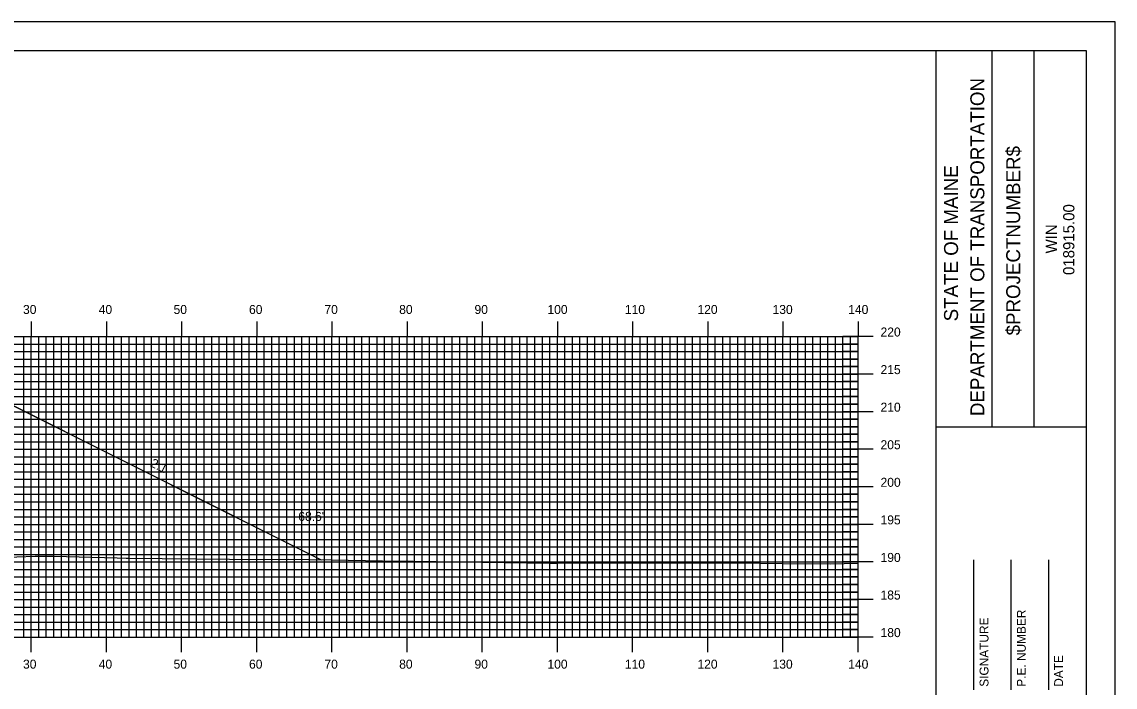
# Model space of a CAD drawing. Extents: x 1810980 to 1811323, y 442591 to 442811.
# Drawn here: x 1811174.6 to 1811320.1, y 442722 to 442810.5 of the extents above; entities that cross this region are included whole.
import ezdxf

# ---------------------------------------------------------------- set-up
doc = ezdxf.new("R2010")
doc.units = 0
for name, color, linetype in [('ANNOTATION', 7, 'Continuous'), ('BORDER', 7, 'Continuous'), ('D_Roadway_Centerline', 7, 'Continuous'), ('D_Roadway_SlopeLines', 7, 'Continuous'), ('D_Text_Standard', 7, 'Continuous'), ('H_V ANNOTATION', 7, 'Continuous'), ('MAJOR', 7, 'Continuous'), ('MINOR', 7, 'Continuous'), ('PLOT BOUNDARY', 7, 'Continuous'), ('S_Roadway_Centerline', 7, 'Continuous')]:
    doc.layers.add(name, color=color, linetype=linetype)

msp = doc.modelspace()

# ---------------------------------------------------------------- linework, layer by layer
at = {"layer": 'BORDER'}
for p, q in [((1811296.29, 442596.67), (1811296.29, 442806.67)), ((1811303.75, 442756.66), (1811303.75, 442806.66)), ((1811309.34, 442756.66), (1811309.34, 442806.66)), ((1811296.29, 442756.65), (1811316.29, 442756.65)), ((1811301.29, 442721.67), (1811301.29, 442738.97)), ((1811306.29, 442721.67), (1811306.29, 442738.97)), ((1811311.29, 442721.67), (1811311.29, 442738.97))]:
    msp.add_line(p, q, dxfattribs=at)
msp.add_lwpolyline([(1810996.29, 442596.67), (1811316.29, 442596.67), (1811316.29, 442806.67), (1810996.29, 442806.67)], close=True, dxfattribs=at)
at = {"layer": 'D_Roadway_Centerline'}
msp.add_lwpolyline([(1811076.55, 442740.06), (1811117.68, 442760.62), (1811122.89, 442763.23), (1811125.89, 442763.29), (1811133.89, 442763.45), (1811145.89, 442762.87), (1811157.89, 442762.29), (1811165.89, 442761.91), (1811168.89, 442761.77), (1811174.42, 442759), (1811214.48, 442738.97)], dxfattribs=at)
at = {"layer": 'D_Roadway_SlopeLines'}
msp.add_lwpolyline([(1811168.89, 442761.77), (1811214.48, 442738.97)], dxfattribs=at)
at = {"layer": 'MAJOR'}
for p, q in [((1811175.89, 442770.67), (1811175.89, 442768.67)), ((1811185.89, 442770.67), (1811185.89, 442768.67)), ((1811195.89, 442770.67), (1811195.89, 442768.67)), ((1811205.89, 442770.67), (1811205.89, 442768.67)), ((1811215.89, 442770.67), (1811215.89, 442768.67)), ((1811225.89, 442770.67), (1811225.89, 442768.67)), ((1811235.89, 442770.67), (1811235.89, 442768.67)), ((1811245.89, 442770.67), (1811245.89, 442768.67)), ((1811255.89, 442770.67), (1811255.89, 442768.67)), ((1811265.89, 442770.67), (1811265.89, 442768.67)), ((1811275.89, 442770.67), (1811275.89, 442768.67)), ((1811285.89, 442770.67), (1811285.89, 442768.67)), ((1811005.89, 442768.67), (1811285.89, 442768.67)), ((1811005.89, 442768.67), (1811285.89, 442768.67)), ((1811175.89, 442728.67), (1811175.89, 442768.67)), ((1811185.89, 442728.67), (1811185.89, 442768.67)), ((1811195.89, 442728.67), (1811195.89, 442768.67)), ((1811205.89, 442728.67), (1811205.89, 442768.67)), ((1811215.89, 442728.67), (1811215.89, 442768.67)), ((1811225.89, 442728.67), (1811225.89, 442768.67)), ((1811235.89, 442728.67), (1811235.89, 442768.67)), ((1811245.89, 442728.67), (1811245.89, 442768.67)), ((1811255.89, 442728.67), (1811255.89, 442768.67)), ((1811265.89, 442728.67), (1811265.89, 442768.67)), ((1811275.89, 442728.67), (1811275.89, 442768.67)), ((1811287.89, 442768.67), (1811283.89, 442768.67)), ((1811285.89, 442728.67), (1811285.89, 442768.67)), ((1811285.89, 442728.67), (1811285.89, 442768.67)), ((1811005.89, 442763.67), (1811285.89, 442763.67)), ((1811287.89, 442763.67), (1811283.89, 442763.67)), ((1811005.89, 442758.67), (1811285.89, 442758.67)), ((1811287.89, 442758.67), (1811283.89, 442758.67)), ((1811005.89, 442753.67), (1811285.89, 442753.67)), ((1811287.89, 442753.67), (1811283.89, 442753.67)), ((1811005.89, 442748.67), (1811285.89, 442748.67)), ((1811287.89, 442748.67), (1811283.89, 442748.67)), ((1811005.89, 442743.67), (1811285.89, 442743.67)), ((1811287.89, 442743.67), (1811283.89, 442743.67)), ((1811005.89, 442738.67), (1811285.89, 442738.67)), ((1811287.89, 442738.67), (1811283.89, 442738.67)), ((1811005.89, 442733.67), (1811285.89, 442733.67)), ((1811287.89, 442733.67), (1811283.89, 442733.67)), ((1811005.89, 442728.67), (1811285.89, 442728.67)), ((1811005.89, 442728.67), (1811285.89, 442728.67)), ((1811175.89, 442726.66), (1811175.89, 442728.67)), ((1811185.89, 442726.66), (1811185.89, 442728.67)), ((1811195.89, 442726.66), (1811195.89, 442728.67)), ((1811205.89, 442726.66), (1811205.89, 442728.67)), ((1811215.89, 442726.66), (1811215.89, 442728.67)), ((1811225.89, 442726.66), (1811225.89, 442728.67)), ((1811235.89, 442726.66), (1811235.89, 442728.67)), ((1811245.89, 442726.66), (1811245.89, 442728.67)), ((1811255.89, 442726.66), (1811255.89, 442728.67)), ((1811265.89, 442726.66), (1811265.89, 442728.67)), ((1811275.89, 442726.66), (1811275.89, 442728.67)), ((1811287.89, 442728.67), (1811283.89, 442728.67)), ((1811285.89, 442726.66), (1811285.89, 442728.67))]:
    msp.add_line(p, q, dxfattribs=at)
at = {"layer": 'MINOR'}
for p, q in [((1811174.89, 442728.67), (1811174.89, 442768.67)), ((1811176.89, 442728.67), (1811176.89, 442768.67)), ((1811177.89, 442728.67), (1811177.89, 442768.67)), ((1811178.89, 442728.67), (1811178.89, 442768.67)), ((1811179.89, 442728.67), (1811179.89, 442768.67)), ((1811180.89, 442728.67), (1811180.89, 442768.67)), ((1811181.89, 442728.67), (1811181.89, 442768.67)), ((1811182.89, 442728.67), (1811182.89, 442768.67)), ((1811183.89, 442728.67), (1811183.89, 442768.67)), ((1811184.89, 442728.67), (1811184.89, 442768.67)), ((1811186.89, 442728.67), (1811186.89, 442768.67)), ((1811187.89, 442728.67), (1811187.89, 442768.67)), ((1811188.89, 442728.67), (1811188.89, 442768.67)), ((1811189.89, 442728.67), (1811189.89, 442768.67)), ((1811190.89, 442728.67), (1811190.89, 442768.67)), ((1811191.89, 442728.67), (1811191.89, 442768.67)), ((1811192.89, 442728.67), (1811192.89, 442768.67)), ((1811193.89, 442728.67), (1811193.89, 442768.67)), ((1811194.89, 442728.67), (1811194.89, 442768.67)), ((1811196.89, 442728.67), (1811196.89, 442768.67)), ((1811197.89, 442728.67), (1811197.89, 442768.67)), ((1811198.89, 442728.67), (1811198.89, 442768.67)), ((1811199.89, 442728.67), (1811199.89, 442768.67)), ((1811200.89, 442728.67), (1811200.89, 442768.67)), ((1811201.89, 442728.67), (1811201.89, 442768.67)), ((1811202.89, 442728.67), (1811202.89, 442768.67)), ((1811203.89, 442728.67), (1811203.89, 442768.67)), ((1811204.89, 442728.67), (1811204.89, 442768.67)), ((1811206.89, 442728.67), (1811206.89, 442768.67)), ((1811207.89, 442728.67), (1811207.89, 442768.67)), ((1811208.89, 442728.67), (1811208.89, 442768.67)), ((1811209.89, 442728.67), (1811209.89, 442768.67)), ((1811210.89, 442728.67), (1811210.89, 442768.67)), ((1811211.89, 442728.67), (1811211.89, 442768.67)), ((1811212.89, 442728.67), (1811212.89, 442768.67)), ((1811213.89, 442728.67), (1811213.89, 442768.67)), ((1811214.89, 442728.67), (1811214.89, 442768.67)), ((1811216.89, 442728.67), (1811216.89, 442768.67)), ((1811217.89, 442728.67), (1811217.89, 442768.67)), ((1811218.89, 442728.67), (1811218.89, 442768.67)), ((1811219.89, 442728.67), (1811219.89, 442768.67)), ((1811220.89, 442728.67), (1811220.89, 442768.67)), ((1811221.89, 442728.67), (1811221.89, 442768.67)), ((1811222.89, 442728.67), (1811222.89, 442768.67)), ((1811223.89, 442728.67), (1811223.89, 442768.67)), ((1811224.89, 442728.67), (1811224.89, 442768.67)), ((1811226.89, 442728.67), (1811226.89, 442768.67)), ((1811227.89, 442728.67), (1811227.89, 442768.67)), ((1811228.89, 442728.67), (1811228.89, 442768.67)), ((1811229.89, 442728.67), (1811229.89, 442768.67)), ((1811230.89, 442728.67), (1811230.89, 442768.67)), ((1811231.89, 442728.67), (1811231.89, 442768.67)), ((1811232.89, 442728.67), (1811232.89, 442768.67)), ((1811233.89, 442728.67), (1811233.89, 442768.67)), ((1811234.89, 442728.67), (1811234.89, 442768.67)), ((1811236.89, 442728.67), (1811236.89, 442768.67)), ((1811237.89, 442728.67), (1811237.89, 442768.67)), ((1811238.89, 442728.67), (1811238.89, 442768.67)), ((1811239.89, 442728.67), (1811239.89, 442768.67)), ((1811240.89, 442728.67), (1811240.89, 442768.67)), ((1811241.89, 442728.67), (1811241.89, 442768.67)), ((1811242.89, 442728.67), (1811242.89, 442768.67)), ((1811243.89, 442728.67), (1811243.89, 442768.67)), ((1811244.89, 442728.67), (1811244.89, 442768.67)), ((1811246.89, 442728.67), (1811246.89, 442768.67)), ((1811247.89, 442728.67), (1811247.89, 442768.67)), ((1811248.89, 442728.67), (1811248.89, 442768.67)), ((1811249.89, 442728.67), (1811249.89, 442768.67)), ((1811250.89, 442728.67), (1811250.89, 442768.67)), ((1811251.89, 442728.67), (1811251.89, 442768.67)), ((1811252.89, 442728.67), (1811252.89, 442768.67)), ((1811253.89, 442728.67), (1811253.89, 442768.67)), ((1811254.89, 442728.67), (1811254.89, 442768.67)), ((1811256.89, 442728.67), (1811256.89, 442768.67)), ((1811257.89, 442728.67), (1811257.89, 442768.67)), ((1811258.89, 442728.67), (1811258.89, 442768.67)), ((1811259.89, 442728.67), (1811259.89, 442768.67)), ((1811260.89, 442728.67), (1811260.89, 442768.67)), ((1811261.89, 442728.67), (1811261.89, 442768.67)), ((1811262.89, 442728.67), (1811262.89, 442768.67)), ((1811263.89, 442728.67), (1811263.89, 442768.67)), ((1811264.89, 442728.67), (1811264.89, 442768.67)), ((1811266.89, 442728.67), (1811266.89, 442768.67)), ((1811267.89, 442728.67), (1811267.89, 442768.67)), ((1811268.89, 442728.67), (1811268.89, 442768.67)), ((1811269.89, 442728.67), (1811269.89, 442768.67)), ((1811270.89, 442728.67), (1811270.89, 442768.67)), ((1811271.89, 442728.67), (1811271.89, 442768.67)), ((1811272.89, 442728.67), (1811272.89, 442768.67)), ((1811273.89, 442728.67), (1811273.89, 442768.67)), ((1811274.89, 442728.67), (1811274.89, 442768.67)), ((1811276.89, 442728.67), (1811276.89, 442768.67)), ((1811277.89, 442728.67), (1811277.89, 442768.67)), ((1811278.89, 442728.67), (1811278.89, 442768.67)), ((1811279.89, 442728.67), (1811279.89, 442768.67)), ((1811280.89, 442728.67), (1811280.89, 442768.67)), ((1811281.89, 442728.67), (1811281.89, 442768.67)), ((1811282.89, 442728.67), (1811282.89, 442768.67)), ((1811283.89, 442728.67), (1811283.89, 442768.67)), ((1811284.89, 442728.67), (1811284.89, 442768.67)), ((1811005.89, 442767.67), (1811285.89, 442767.67)), ((1811285.89, 442767.67), (1811283.89, 442767.67)), ((1811005.89, 442766.67), (1811285.89, 442766.67)), ((1811005.89, 442765.67), (1811285.89, 442765.67)), ((1811285.89, 442766.67), (1811283.89, 442766.67)), ((1811285.89, 442765.67), (1811283.89, 442765.67)), ((1811005.89, 442764.67), (1811285.89, 442764.67)), ((1811285.89, 442764.67), (1811283.89, 442764.67)), ((1811005.89, 442762.67), (1811285.89, 442762.67)), ((1811285.89, 442762.67), (1811283.89, 442762.67)), ((1811005.89, 442761.67), (1811285.89, 442761.67)), ((1811285.89, 442761.67), (1811283.89, 442761.67)), ((1811005.89, 442760.67), (1811285.89, 442760.67)), ((1811285.89, 442760.67), (1811283.89, 442760.67)), ((1811005.89, 442759.67), (1811285.89, 442759.67)), ((1811285.89, 442759.67), (1811283.89, 442759.67)), ((1811005.89, 442757.67), (1811285.89, 442757.67)), ((1811285.89, 442757.67), (1811283.89, 442757.67)), ((1811005.89, 442756.67), (1811285.89, 442756.67)), ((1811005.89, 442755.67), (1811285.89, 442755.67)), ((1811285.89, 442756.67), (1811283.89, 442756.67)), ((1811285.89, 442755.67), (1811283.89, 442755.67)), ((1811005.89, 442754.67), (1811285.89, 442754.67)), ((1811285.89, 442754.67), (1811283.89, 442754.67)), ((1811005.89, 442752.67), (1811285.89, 442752.67)), ((1811285.89, 442752.67), (1811283.89, 442752.67)), ((1811005.89, 442751.67), (1811285.89, 442751.67)), ((1811285.89, 442751.67), (1811283.89, 442751.67)), ((1811005.89, 442750.67), (1811285.89, 442750.67)), ((1811005.89, 442749.67), (1811285.89, 442749.67)), ((1811285.89, 442750.67), (1811283.89, 442750.67)), ((1811285.89, 442749.67), (1811283.89, 442749.67)), ((1811005.89, 442747.67), (1811285.89, 442747.67)), ((1811005.89, 442746.67), (1811285.89, 442746.67)), ((1811285.89, 442747.67), (1811283.89, 442747.67)), ((1811285.89, 442746.67), (1811283.89, 442746.67)), ((1811005.89, 442745.67), (1811285.89, 442745.67)), ((1811285.89, 442745.67), (1811283.89, 442745.67)), ((1811005.89, 442744.67), (1811285.89, 442744.67)), ((1811285.89, 442744.67), (1811283.89, 442744.67)), ((1811005.89, 442742.67), (1811285.89, 442742.67)), ((1811285.89, 442742.67), (1811283.89, 442742.67)), ((1811005.89, 442741.67), (1811285.89, 442741.67)), ((1811285.89, 442741.67), (1811283.89, 442741.67)), ((1811005.89, 442740.67), (1811285.89, 442740.67)), ((1811005.89, 442739.67), (1811285.89, 442739.67)), ((1811285.89, 442740.67), (1811283.89, 442740.67)), ((1811285.89, 442739.67), (1811283.89, 442739.67)), ((1811005.89, 442737.67), (1811285.89, 442737.67)), ((1811005.89, 442736.67), (1811285.89, 442736.67)), ((1811285.89, 442737.67), (1811283.89, 442737.67)), ((1811285.89, 442736.67), (1811283.89, 442736.67)), ((1811005.89, 442735.67), (1811285.89, 442735.67)), ((1811285.89, 442735.67), (1811283.89, 442735.67)), ((1811005.89, 442734.67), (1811285.89, 442734.67)), ((1811285.89, 442734.67), (1811283.89, 442734.67)), ((1811005.89, 442732.67), (1811285.89, 442732.67)), ((1811285.89, 442732.67), (1811283.89, 442732.67)), ((1811005.89, 442731.67), (1811285.89, 442731.67)), ((1811005.89, 442730.67), (1811285.89, 442730.67)), ((1811285.89, 442731.67), (1811283.89, 442731.67)), ((1811285.89, 442730.67), (1811283.89, 442730.67)), ((1811005.89, 442729.67), (1811285.89, 442729.67)), ((1811285.89, 442729.67), (1811283.89, 442729.67))]:
    msp.add_line(p, q, dxfattribs=at)
at = {"layer": 'PLOT BOUNDARY'}
msp.add_lwpolyline([(1810980.1, 442590.55), (1811320.1, 442590.55), (1811320.1, 442810.55), (1810980.1, 442810.55)], close=True, dxfattribs=at)
at = {"layer": 'S_Roadway_Centerline'}
msp.add_lwpolyline([(1811166.62, 442739.1), (1811176.41, 442739.44), (1811178.91, 442739.42), (1811187.33, 442739.23), (1811188.53, 442739.18), (1811188.84, 442739.18), (1811206.76, 442739.01), (1811210.15, 442739.06), (1811215.78, 442738.94), (1811222.63, 442738.83), (1811226.72, 442738.76), (1811244.94, 442738.51), (1811245.52, 442738.51), (1811245.63, 442738.5), (1811245.9, 442738.51), (1811258.53, 442738.54), (1811266.02, 442738.56), (1811269.99, 442738.55), (1811275.81, 442738.47), (1811282.17, 442738.41), (1811285.89, 442738.52)], dxfattribs=at)

# ---------------------------------------------------------------- texts
at = {"layer": 'ANNOTATION'}
msp.add_text('2:1', height=1.2, rotation=333.4349, dxfattribs=at).set_placement((1811191.62, 442751.44))
at = {"layer": 'BORDER'}
for s, height, p in [('DEPARTMENT OF TRANSPORTATION', 1.8635, (1811302.7, 442758.08)), ('$PROJECTNUMBER$', 1.8635, (1811307.47, 442768.82)), ('STATE OF MAINE', 1.8635, (1811299.2, 442770.69)), ('018915.00', 1.491, (1811314.68, 442776.86)), ('WIN', 1.491, (1811312.36, 442779.73)), ('P.E. NUMBER', 1.1811, (1811308.21, 442722.06)), ('SIGNATURE', 1.181, (1811303.25, 442722.06)), ('DATE', 1.181, (1811313.17, 442722.06))]:
    msp.add_text(s, height=height, rotation=90, dxfattribs=at).set_placement(p)
at = {"layer": 'D_Text_Standard'}
msp.add_text("68.6'", height=1.2, dxfattribs=at).set_placement((1811211.42, 442744.13))
at = {"layer": 'H_V ANNOTATION'}
for s, p in [('30', (1811174.79, 442771.67)), ('40', (1811184.86, 442771.67)), ('50', (1811194.82, 442771.67)), ('60', (1811204.86, 442771.67)), ('70', (1811214.89, 442771.67)), ('80', (1811224.84, 442771.67)), ('90', (1811234.86, 442771.67)), ('100', (1811244.57, 442771.67)), ('110', (1811254.87, 442771.67)), ('120', (1811264.53, 442771.67)), ('130', (1811274.52, 442771.67)), ('140', (1811284.59, 442771.67)), ('220', (1811288.89, 442768.67)), ('215', (1811288.89, 442763.67)), ('210', (1811288.89, 442758.67)), ('205', (1811288.89, 442753.67)), ('200', (1811288.89, 442748.67)), ('195', (1811288.89, 442743.67)), ('190', (1811288.89, 442738.67)), ('185', (1811288.89, 442733.67)), ('180', (1811288.89, 442728.67)), ('30', (1811174.79, 442724.47)), ('40', (1811184.86, 442724.47)), ('50', (1811194.82, 442724.47)), ('60', (1811204.86, 442724.47)), ('70', (1811214.89, 442724.47)), ('80', (1811224.84, 442724.47)), ('90', (1811234.86, 442724.47)), ('100', (1811244.57, 442724.47)), ('110', (1811254.87, 442724.47)), ('120', (1811264.53, 442724.47)), ('130', (1811274.52, 442724.47)), ('140', (1811284.59, 442724.47))]:
    msp.add_text(s, height=1.2, dxfattribs=at).set_placement(p)

doc.saveas('drawing.dxf')
